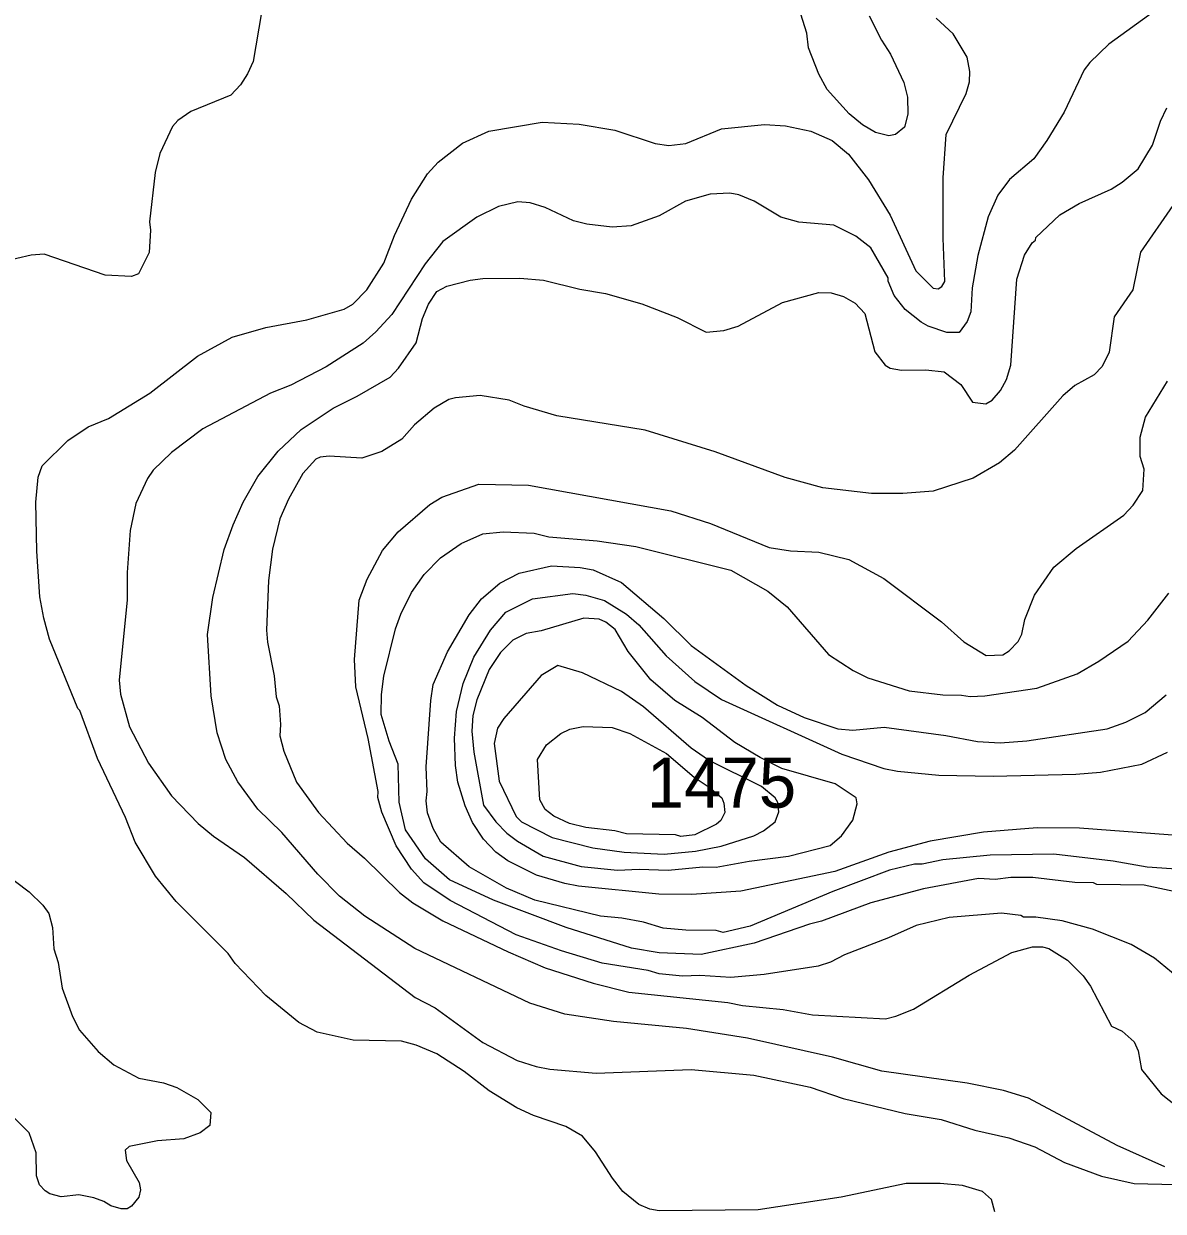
# Model space of a CAD drawing. Extents: x 598.3 to 623.2, y 6902.2 to 6930.1.
# Drawn here: x 604.628 to 606.443, y 6914.609 to 6916.5 of the extents above; entities that cross this region are included whole.
import ezdxf

# ---------------------------------------------------------------- set-up
doc = ezdxf.new("R2010")
doc.units = 0
doc.header["$LTSCALE"] = 0.032
doc.layers.add('1', color=7, linetype='Continuous', lineweight=25)
doc.layers.add('2', color=7, linetype='Continuous', lineweight=13)
doc.layers.add('21', color=7, linetype='Continuous')

msp = doc.modelspace()

# ---------------------------------------------------------------- linework, layer by layer
at = {"layer": '1'}
for points in [[(604.9618, 6915.7023), (604.9781, 6915.7382), (605.0012, 6915.7793), (605.0338, 6915.8194), (605.0702, 6915.8541), (605.1213, 6915.888), (605.1595, 6915.9071), (605.2118, 6915.9376), (605.2253, 6915.9515), (605.2532, 6915.9921), (605.2637, 6916.031), (605.2731, 6916.0537), (605.2862, 6916.074), (605.3023, 6916.0821), (605.3396, 6916.0918), (605.3597, 6916.0943), (605.4187, 6916.095), (605.4561, 6916.0918), (605.5141, 6916.0773), (605.5547, 6916.0704), (605.6129, 6916.0542), (605.6692, 6916.0322), (605.7152, 6916.0093), (605.7436, 6916.0118), (605.7663, 6916.0187), (605.8366, 6916.0562), (605.8946, 6916.0724), (605.9143, 6916.0715), (605.9337, 6916.0659), (605.9525, 6916.055), (605.9681, 6916.0388), (605.9837, 6915.9776), (606.0005, 6915.9564), (606.0081, 6915.9516), (606.0263, 6915.9485), (606.0652, 6915.9493), (606.0943, 6915.946), (606.1207, 6915.9259), (606.1394, 6915.8977), (606.1604, 6915.8952), (606.1709, 6915.9008), (606.184, 6915.9164), (606.1934, 6915.9337), (606.2006, 6915.9567), (606.2098, 6916.0937), (606.2224, 6916.1317), (606.2344, 6916.1511), (606.2395, 6916.1556), (606.24, 6916.16), (606.2783, 6916.196), (606.3093, 6916.214), (606.3601, 6916.2366), (606.3775, 6916.2478), (606.4034, 6916.2694), (606.4258, 6916.3069), (606.4386, 6916.3453), (606.4489, 6916.3661)], [(606.4456, 6914.6799), (606.3699, 6914.7138), (606.2287, 6914.7892), (606.1888, 6914.8017), (606.1309, 6914.8129), (605.9949, 6914.8323), (605.9162, 6914.8545), (605.7808, 6914.885), (605.6841, 6914.9003), (605.5678, 6914.9116), (605.4904, 6914.9229), (605.4342, 6914.9406), (605.2515, 6915.0277), (605.1719, 6915.079), (605.1313, 6915.111), (605.0969, 6915.1461), (605.0394, 6915.2125), (605.0015, 6915.2497), (604.9693, 6915.293), (604.9505, 6915.3287), (604.9365, 6915.3711), (604.9267, 6915.4299), (604.9211, 6915.5275), (604.9294, 6915.5865), (604.9478, 6915.6631), (604.9618, 6915.7023)], [(606.5001, 6915.2047), (606.31, 6915.2192), (606.2426, 6915.22), (606.1568, 6915.2127), (606.072, 6915.1983), (606.0059, 6915.1809), (605.9201, 6915.1502), (605.7705, 6915.1189), (605.6919, 6915.1134), (605.64, 6915.114), (605.5119, 6915.1268), (605.4901, 6915.1309), (605.4451, 6915.1446), (605.3993, 6915.1673), (605.3804, 6915.181), (605.3604, 6915.2015), (605.3429, 6915.2282), (605.3314, 6915.2548), (605.3198, 6915.2927), (605.3161, 6915.3189), (605.3145, 6915.3624), (605.3177, 6915.4051), (605.3285, 6915.4498), (605.3454, 6915.4915), (605.3718, 6915.5347), (605.3963, 6915.5632), (605.4386, 6915.5843), (605.5031, 6915.5931), (605.5238, 6915.59), (605.5532, 6915.5818), (605.5886, 6915.5602), (605.6081, 6915.5432), (605.6514, 6915.4935), (605.6972, 6915.4526), (605.7394, 6915.424), (605.9311, 6915.3368), (605.9982, 6915.314), (606.0198, 6915.3098), (606.0856, 6915.3034), (606.1724, 6915.3018), (606.3037, 6915.3052), (606.3433, 6915.3082), (606.409, 6915.3211), (606.45, 6915.3405)]]:
    msp.add_lwpolyline(points, dxfattribs=at)
at = {"layer": '2'}
for points in [[(605.8945, 6916.4197), (605.878, 6916.462), (605.8754, 6916.4852), (605.857, 6916.5446)], [(605.0069, 6916.5179), (604.9939, 6916.4399), (604.9849, 6916.4203), (604.9737, 6916.4031), (604.9582, 6916.3865), (604.8944, 6916.3606), (604.8736, 6916.3462), (604.8655, 6916.3366), (604.8453, 6916.2936), (604.8377, 6916.2631), (604.8288, 6916.1847), (604.8304, 6916.1717), (604.8281, 6916.1358), (604.8111, 6916.1018), (604.8001, 6916.0975), (604.7582, 6916.0996), (604.6612, 6916.1331), (604.64, 6916.1315), (604.5948, 6916.1209)], [(604.654, 6915.5878), (604.6491, 6915.6603), (604.6475, 6915.7382), (604.6516, 6915.778), (604.658, 6915.7963), (604.6984, 6915.8368), (604.7313, 6915.8581), (604.7635, 6915.8717), (604.8294, 6915.912), (604.9051, 6915.9706), (604.9602, 6916.0009), (605.0142, 6916.0165), (605.0792, 6916.0288), (605.1386, 6916.0456), (605.1525, 6916.0538), (605.1746, 6916.0767), (605.2018, 6916.1191), (605.2188, 6916.1628), (605.246, 6916.2206), (605.2716, 6916.261), (605.2885, 6916.2796), (605.3272, 6916.3103), (605.369, 6916.3291), (605.454, 6916.3435), (605.5131, 6916.3403), (605.5698, 6916.3306), (605.634, 6916.3096), (605.6559, 6916.3063), (605.6831, 6916.3096), (605.7394, 6916.333), (605.8081, 6916.3396), (605.8417, 6916.3379), (605.8817, 6916.3291), (605.9161, 6916.3143), (605.942, 6916.2923), (605.9736, 6916.2519), (606.0081, 6916.1956), (606.0491, 6916.1069), (606.0769, 6916.0793), (606.0848, 6916.0781), (606.0908, 6916.0816), (606.0955, 6916.0896), (606.0924, 6916.1586), (606.0924, 6916.2547), (606.0973, 6916.3236), (606.1292, 6916.3891), (606.1345, 6916.4075), (606.1353, 6916.4243), (606.1308, 6916.4472), (606.1086, 6916.4842), (606.0815, 6916.5091)], [(606.4293, 6916.5202), (606.3566, 6916.4676), (606.3265, 6916.4385), (606.3173, 6916.4267), (606.2853, 6916.3596), (606.2577, 6916.3142), (606.2368, 6916.285), (606.1984, 6916.2521), (606.1795, 6916.2273), (606.1641, 6916.1928), (606.148, 6916.1314), (606.1388, 6916.0798), (606.1365, 6916.0416), (606.1307, 6916.0259), (606.1179, 6916.0088), (606.0987, 6916.0085), (606.0687, 6916.0187), (606.0574, 6916.0248), (606.0322, 6916.0452), (606.0148, 6916.0675), (606.005, 6916.0905), (606.0049, 6916.0956), (605.9774, 6916.1436), (605.9534, 6916.1621), (605.9187, 6916.1792), (605.8628, 6916.1841), (605.8339, 6916.1922), (605.7919, 6916.2175), (605.7673, 6916.2278), (605.7531, 6916.2303), (605.7216, 6916.2286), (605.6823, 6916.2179), (605.6402, 6916.1943), (605.5957, 6916.1785), (605.5656, 6916.1761), (605.5251, 6916.1809), (605.5041, 6916.1862), (605.4588, 6916.2074), (605.4349, 6916.2149), (605.4154, 6916.2165), (605.3843, 6916.209), (605.3499, 6916.1924), (605.296, 6916.1535), (605.2675, 6916.1177), (605.2146, 6916.037), (605.1892, 6916.0094), (605.1688, 6915.9915)], [(605.9749, 6916.513), (605.9944, 6916.4739), (606.0089, 6916.4515), (606.0298, 6916.4065), (606.0357, 6916.3833), (606.0366, 6916.3564), (606.0309, 6916.3357), (606.0165, 6916.3236), (606.0059, 6916.3218), (605.985, 6916.327), (605.964, 6916.3391), (605.9428, 6916.3565), (605.9078, 6916.3954), (605.8945, 6916.4197)], [(606.4584, 6916.211), (606.407, 6916.1366), (606.3947, 6916.0766), (606.3652, 6916.0335), (606.3572, 6915.9772), (606.3458, 6915.9546), (606.3334, 6915.9411), (606.3026, 6915.9241), (606.2831, 6915.9078), (606.2064, 6915.8214), (606.1822, 6915.801), (606.1404, 6915.7767), (606.0765, 6915.7559), (606.0285, 6915.7519), (605.9786, 6915.7519), (605.9012, 6915.7612), (605.8412, 6915.7778)], [(605.1688, 6915.9915), (605.1103, 6915.9537), (605.0536, 6915.9245), (605.0215, 6915.9118), (604.9136, 6915.8553), (604.8636, 6915.8174), (604.8346, 6915.7892), (604.8254, 6915.7759), (604.8071, 6915.7362), (604.798, 6915.6933), (604.7932, 6915.6261), (604.7931, 6915.5829), (604.7803, 6915.4549), (604.7827, 6915.4327), (604.7967, 6915.3805), (604.8273, 6915.3228), (604.8637, 6915.2709), (604.9064, 6915.2265), (604.9305, 6915.2064), (604.9799, 6915.1724), (605.0462, 6915.1151), (605.0902, 6915.0727), (605.2519, 6914.9498), (605.2835, 6914.9331), (605.3597, 6914.8781), (605.4144, 6914.8492), (605.4443, 6914.8397), (605.4665, 6914.8356), (605.5398, 6914.8291), (605.6915, 6914.8347), (605.7911, 6914.8259), (605.8809, 6914.807), (605.9336, 6914.7889), (606.0319, 6914.7648), (606.0894, 6914.7553), (606.1433, 6914.7382), (606.1974, 6914.7263), (606.2384, 6914.7115), (606.2859, 6914.687), (606.3447, 6914.6648), (606.3971, 6914.6533), (606.4626, 6914.6518)], [(605.6229, 6914.9925), (605.5494, 6915.0044), (605.4846, 6915.0238), (605.4129, 6915.0494), (605.3078, 6915.1039), (605.2657, 6915.1319), (605.246, 6915.1539), (605.2217, 6915.1909), (605.1989, 6915.2445), (605.1923, 6915.2678), (605.193, 6915.2775), (605.1767, 6915.3622), (605.1574, 6915.4442), (605.155, 6915.4879), (605.1624, 6915.5821), (605.1751, 6915.6156), (605.1997, 6915.6615), (605.2246, 6915.6911), (605.2749, 6915.7348), (605.2942, 6915.7461), (605.3532, 6915.7669), (605.4321, 6915.7656), (605.6588, 6915.7243), (605.7223, 6915.7044), (605.8155, 6915.6661), (605.8498, 6915.6611), (605.8949, 6915.6587), (605.9425, 6915.647), (605.9983, 6915.6168), (606.09, 6915.5477), (606.1254, 6915.5162), (606.1611, 6915.4944), (606.1877, 6915.4953), (606.1976, 6915.5017), (606.2119, 6915.5165), (606.2178, 6915.5284), (606.2229, 6915.5515), (606.2383, 6915.5902), (606.2687, 6915.635), (606.3045, 6915.6644), (606.3802, 6915.7174), (606.3955, 6915.7335), (606.4105, 6915.7571), (606.4129, 6915.7907), (606.4066, 6915.8111), (606.4066, 6915.8419), (606.415, 6915.8739), (606.4498, 6915.931)], [(605.8412, 6915.7778), (605.7295, 6915.8183), (605.6183, 6915.853), (605.4775, 6915.8757), (605.4252, 6915.8911), (605.4014, 6915.9008), (605.3552, 6915.908), (605.3162, 6915.9047), (605.3056, 6915.9016), (605.2818, 6915.8882), (605.2507, 6915.8613), (605.2306, 6915.8388), (605.1985, 6915.8189), (605.1666, 6915.8086), (605.1149, 6915.8118), (605.1004, 6915.8102), (605.0937, 6915.8068), (605.0731, 6915.784), (605.0503, 6915.7432), (605.0361, 6915.7117), (605.0244, 6915.6635), (605.0183, 6915.6135), (605.015, 6915.5343), (605.0165, 6915.5155), (605.0272, 6915.4618), (605.0303, 6915.4283), (605.0352, 6915.414), (605.0375, 6915.3841), (605.0361, 6915.366), (605.0426, 6915.3417), (605.0626, 6915.2923), (605.0977, 6915.2442), (605.1435, 6915.1951), (605.1709, 6915.1716), (605.2271, 6915.1169), (605.248, 6915.1004), (605.2958, 6915.0718), (605.4, 6915.0222), (605.4589, 6914.9968), (605.5353, 6914.9724), (605.5922, 6914.9582), (605.7495, 6914.9415), (605.7732, 6914.9367), (605.838, 6914.9303), (605.8845, 6914.922), (606.0007, 6914.9157), (606.0173, 6914.9197), (606.0452, 6914.9309), (606.1343, 6914.9851), (606.202, 6915.0214), (606.2347, 6915.0305), (606.251, 6915.0305), (606.2611, 6915.0275), (606.2905, 6915.0089), (606.3154, 6914.984), (606.3274, 6914.9677), (606.361, 6914.9038), (606.3778, 6914.8959), (606.3966, 6914.8792), (606.4034, 6914.8647), (606.4083, 6914.8347), (606.44, 6914.7963), (606.4909, 6914.756)], [(605.7071, 6915.0178), (605.6402, 6915.0209), (605.5964, 6915.0283), (605.4923, 6915.0613), (605.3768, 6915.1047), (605.3063, 6915.1372), (605.2685, 6915.1704), (605.2366, 6915.2166), (605.2261, 6915.2607), (605.2246, 6915.321), (605.2105, 6915.3578), (605.1978, 6915.4), (605.198, 6915.4319), (605.2017, 6915.4611), (605.2206, 6915.5368), (605.2289, 6915.5598), (605.2458, 6915.5947), (605.2659, 6915.6231), (605.2924, 6915.6496), (605.3248, 6915.6724), (605.3593, 6915.6879), (605.3919, 6915.6911), (605.4411, 6915.6888), (605.4645, 6915.683), (605.5417, 6915.6766), (605.6032, 6915.6677), (605.7543, 6915.6303), (605.8137, 6915.5966), (605.8443, 6915.5717), (605.9099, 6915.4956), (605.9496, 6915.4702), (605.9729, 6915.4587), (606.0384, 6915.4379), (606.0919, 6915.4313), (606.1218, 6915.4312), (606.1355, 6915.4288), (606.1592, 6915.4298), (606.2416, 6915.4419), (606.3059, 6915.4651), (606.3404, 6915.4849), (606.3874, 6915.517), (606.4187, 6915.5502), (606.4518, 6915.5932)], [(606.4715, 6915.1536), (606.4177, 6915.157), (606.3633, 6915.1665), (606.2691, 6915.1779), (606.1675, 6915.1764), (606.0922, 6915.169), (606.0594, 6915.1619), (606.0468, 6915.1617), (606.0072, 6915.1522), (605.9169, 6915.1186), (605.7854, 6915.0632), (605.7425, 6915.0532), (605.7313, 6915.0564), (605.6826, 6915.0567), (605.647, 6915.0602), (605.6154, 6915.0693), (605.5811, 6915.0759), (605.5471, 6915.0791), (605.4426, 6915.1047), (605.3973, 6915.1239), (605.3379, 6915.1576), (605.2925, 6915.1968), (605.2807, 6915.2187), (605.2716, 6915.2439), (605.2692, 6915.2628), (605.2708, 6915.2774), (605.2692, 6915.3169), (605.2767, 6915.4225), (605.2805, 6915.448), (605.3034, 6915.5001), (605.3379, 6915.5592), (605.3575, 6915.5844), (605.3868, 6915.6095), (605.4173, 6915.6255), (605.4691, 6915.6369), (605.5147, 6915.6344), (605.5353, 6915.6305), (605.5806, 6915.6103), (605.6476, 6915.5531), (605.6914, 6915.5102), (605.7788, 6915.4466), (605.8288, 6915.415)], [(606.1749, 6914.6084), (606.1697, 6914.6279), (606.1555, 6914.6404), (606.1236, 6914.6501), (606.0878, 6914.6533), (606.0336, 6914.6534), (605.9303, 6914.6315), (605.7983, 6914.6113), (605.6402, 6914.6097), (605.6254, 6914.6126), (605.6078, 6914.6197), (605.5824, 6914.6406), (605.5659, 6914.662), (605.5391, 6914.7039), (605.5183, 6914.7287), (605.492, 6914.7439), (605.4402, 6914.7617), (605.4138, 6914.7741), (605.3695, 6914.8011), (605.3296, 6914.8316), (605.2864, 6914.8596), (605.2536, 6914.8736), (605.2301, 6914.8799), (605.1529, 6914.8817), (605.0959, 6914.8941), (605.0668, 6914.9095), (605.0139, 6914.953), (604.9651, 6915.0038), (604.9539, 6915.0196), (604.871, 6915.1024), (604.8381, 6915.1428), (604.8059, 6915.197), (604.7903, 6915.2362), (604.7458, 6915.3301), (604.7179, 6915.4068), (604.7147, 6915.4097), (604.6697, 6915.5201), (604.6602, 6915.5537), (604.654, 6915.5878)], [(605.8288, 6915.415), (605.8712, 6915.3954), (605.925, 6915.3775), (605.9489, 6915.3755), (605.9988, 6915.3802), (606.0967, 6915.3666), (606.1473, 6915.357), (606.1836, 6915.3553), (606.2259, 6915.3583), (606.3538, 6915.3776), (606.3836, 6915.3882), (606.4144, 6915.4036), (606.448, 6915.4316)], [(604.5935, 6915.151), (604.6372, 6915.1178), (604.6586, 6915.0964), (604.6685, 6915.0832), (604.6741, 6915.061), (604.6766, 6915.0268), (604.6831, 6915.0053), (604.6897, 6914.9645), (604.706, 6914.9191), (604.7175, 6914.8976), (604.747, 6914.8638), (604.7717, 6914.8423), (604.8118, 6914.821), (604.8509, 6914.8136), (604.8723, 6914.8061), (604.9055, 6914.7871), (604.9266, 6914.7667), (604.9249, 6914.7455), (604.9096, 6914.7338), (604.8836, 6914.7247)], [(606.4776, 6915.1144), (606.4127, 6915.1286), (606.3372, 6915.1294), (606.3322, 6915.1319), (606.3022, 6915.1326), (606.2355, 6915.1406), (606.2003, 6915.1406), (606.1757, 6915.1375), (606.149, 6915.139), (606.0614, 6915.1228), (605.9777, 6915.1003), (605.8987, 6915.0712), (605.8797, 6915.0666), (605.7916, 6915.0363), (605.7071, 6915.0178)], [(606.4741, 6914.9751), (606.4294, 6915.012), (606.3922, 6915.0337), (606.3306, 6915.0583), (606.2821, 6915.0718), (606.24, 6915.0775), (606.2204, 6915.0776), (606.2165, 6915.08), (606.1854, 6915.0841), (606.1024, 6915.0768), (606.0497, 6915.0643), (606.0056, 6915.0446), (605.9353, 6915.0176), (605.9133, 6915.0057), (605.8936, 6914.9992), (605.8077, 6914.9861), (605.7545, 6914.9814), (605.7049, 6914.9845), (605.6774, 6914.9837), (605.6405, 6914.9875), (605.6229, 6914.9925)], [(604.8836, 6914.7247), (604.8412, 6914.7214), (604.7962, 6914.7125), (604.7901, 6914.7067), (604.7923, 6914.6899), (604.8124, 6914.6548), (604.8143, 6914.6434), (604.8116, 6914.6314), (604.7999, 6914.6172), (604.7931, 6914.613), (604.7835, 6914.6129), (604.767, 6914.6176), (604.7562, 6914.6249), (604.7403, 6914.6308), (604.7163, 6914.6355), (604.6882, 6914.6324), (604.6699, 6914.6369), (604.6623, 6914.6416), (604.6537, 6914.6513), (604.6486, 6914.6657), (604.6483, 6914.7022), (604.6369, 6914.7342), (604.6116, 6914.7596)]]:
    msp.add_lwpolyline(points, dxfattribs=at)
for points in [[(605.949, 6915.232), (605.9555, 6915.258), (605.9539, 6915.2677), (605.9207, 6915.2896), (605.8358, 6915.3143), (605.8013, 6915.3316), (605.7607, 6915.3559), (605.7087, 6915.3956), (605.6653, 6915.4227), (605.6271, 6915.4556), (605.5909, 6915.5004), (605.5702, 6915.5357), (605.5557, 6915.547), (605.545, 6915.552), (605.5204, 6915.5534), (605.4523, 6915.5334), (605.4286, 6915.5292), (605.4075, 6915.5187), (605.3877, 6915.4989), (605.3697, 6915.4719), (605.3502, 6915.4235), (605.3436, 6915.3987), (605.3421, 6915.3737), (605.3453, 6915.3401), (605.3607, 6915.2559), (605.3804, 6915.2294), (605.3976, 6915.2113), (605.4149, 6915.1984), (605.4559, 6915.1747), (605.5163, 6915.1584), (605.5738, 6915.1521), (605.6087, 6915.1537), (605.6549, 6915.1521), (605.7098, 6915.1576), (605.7313, 6915.1569), (605.7838, 6915.1666), (605.8466, 6915.1747), (605.9126, 6915.1917), (605.9307, 6915.2072)], [(605.4788, 6915.4782), (605.4523, 6915.4622), (605.3928, 6915.3939), (605.383, 6915.3786), (605.3777, 6915.3541), (605.3858, 6915.2939), (605.4128, 6915.2379), (605.421, 6915.2291), (605.4699, 6915.2042), (605.535, 6915.1877), (605.5849, 6915.181), (605.6484, 6915.1779), (605.698, 6915.1828), (605.7391, 6915.1905), (605.7911, 6915.2069), (605.8067, 6915.2149), (605.8249, 6915.2295), (605.8309, 6915.2452), (605.8293, 6915.2602), (605.8252, 6915.2676), (605.8034, 6915.2855), (605.7192, 6915.3274), (605.6916, 6915.3464), (605.6156, 6915.4125), (605.5803, 6915.4368), (605.5185, 6915.4664)], [(605.5196, 6915.381), (605.5654, 6915.3797), (605.5935, 6915.3698), (605.652, 6915.3381), (605.6959, 6915.3006), (605.72, 6915.2847), (605.7402, 6915.2675), (605.7436, 6915.2592), (605.7452, 6915.2441), (605.7386, 6915.2313), (605.7315, 6915.2257), (605.6971, 6915.2086), (605.6748, 6915.2062), (605.6666, 6915.2086), (605.5881, 6915.2104), (605.5698, 6915.2151), (605.5236, 6915.2201), (605.4974, 6915.2267), (605.4725, 6915.2385), (605.4587, 6915.249), (605.4501, 6915.2645), (605.4466, 6915.3284), (605.4609, 6915.3518), (605.4838, 6915.3699), (605.4982, 6915.377)]]:
    msp.add_lwpolyline(points, close=True, dxfattribs=at)

# ---------------------------------------------------------------- texts
at = {"layer": '21'}
msp.add_text('1475', height=0.08, dxfattribs=at).set_placement((605.6206, 6915.2517))

doc.saveas('drawing.dxf')
